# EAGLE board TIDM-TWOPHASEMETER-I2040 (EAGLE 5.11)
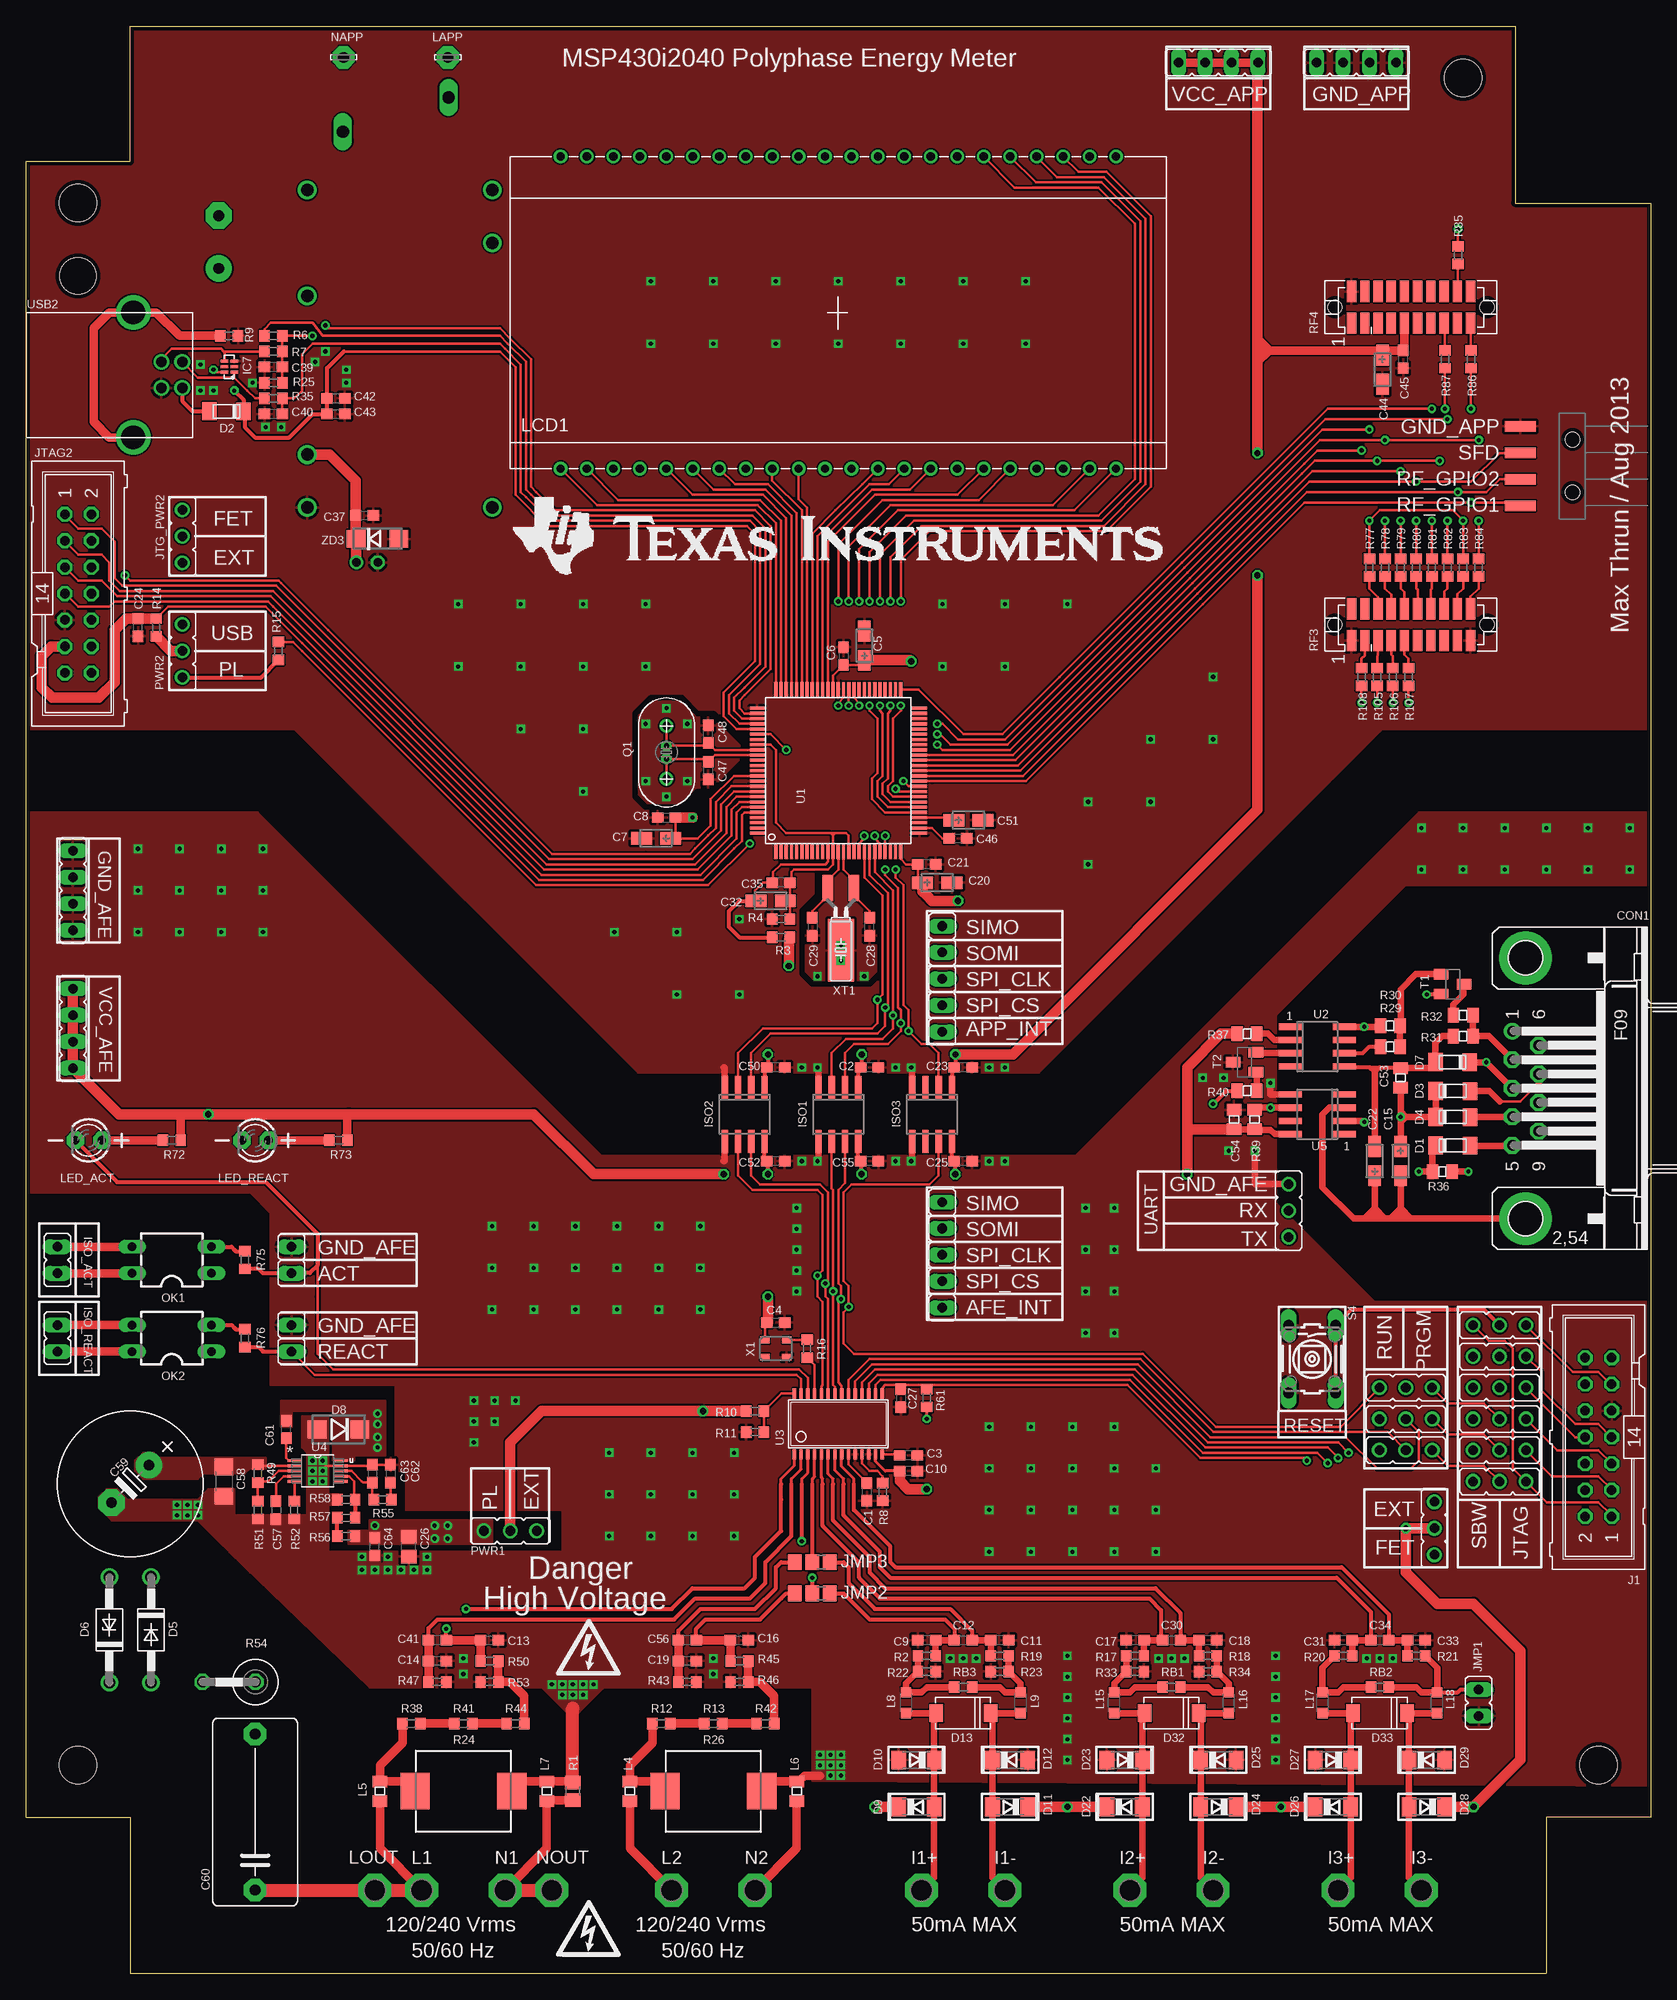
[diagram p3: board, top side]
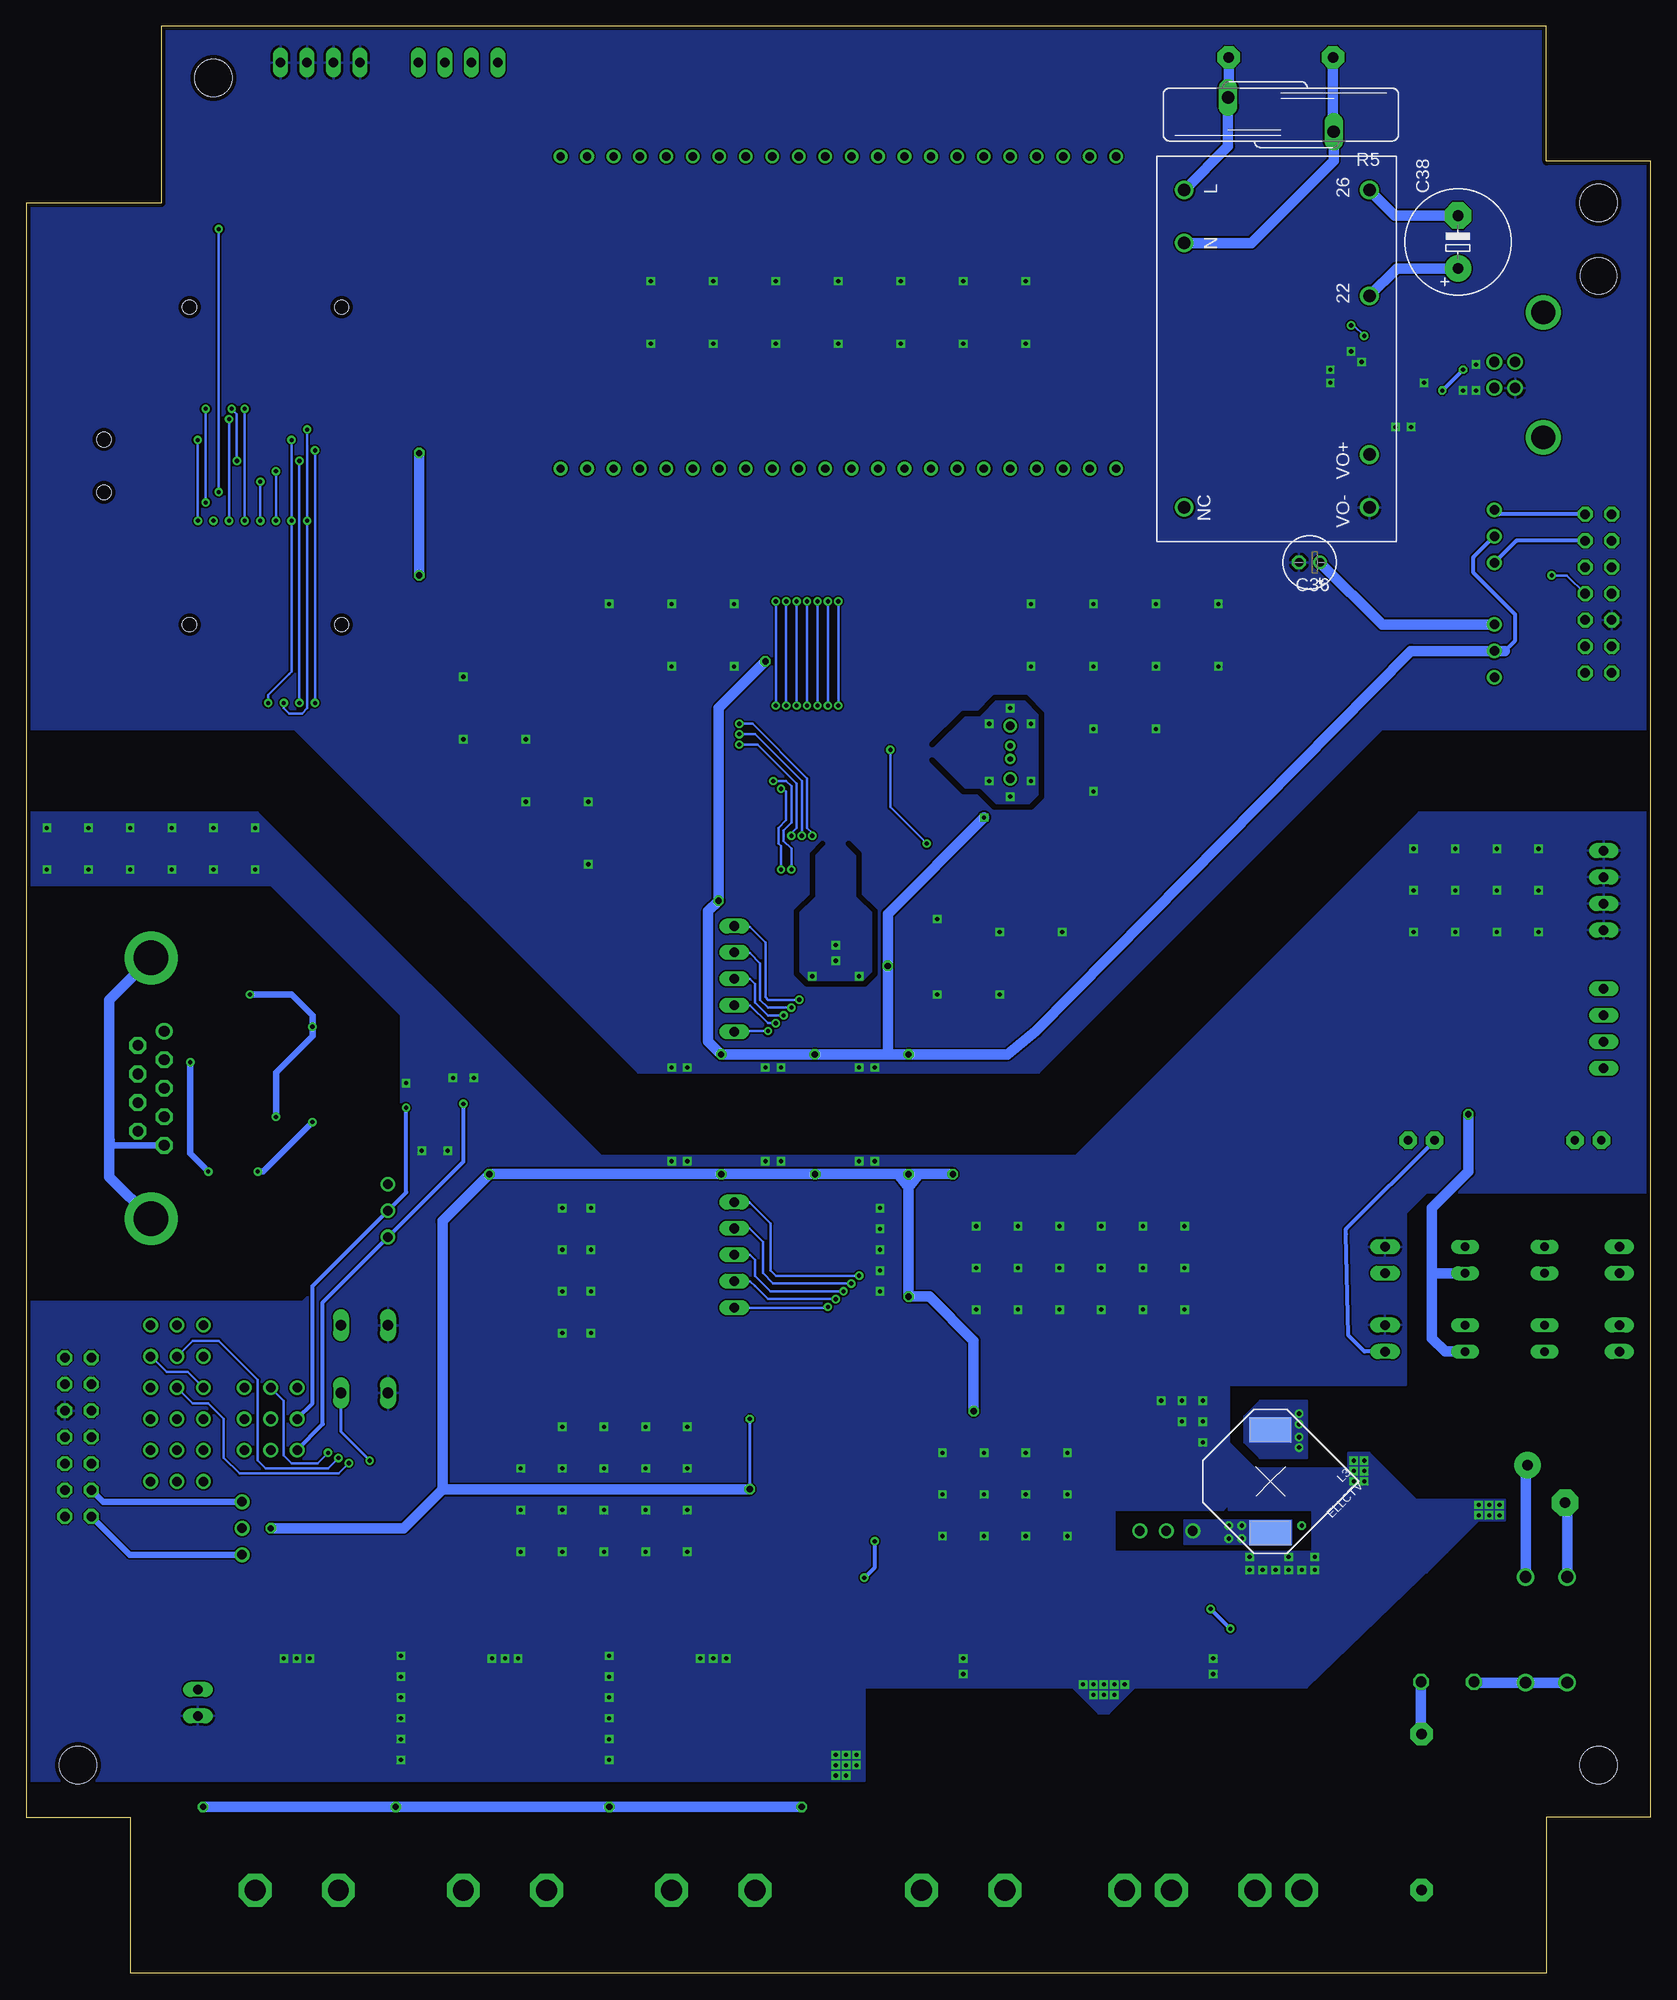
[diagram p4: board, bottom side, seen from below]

Size 156 x 187 mm. Coordinates in mm from the lower left corner, seen from the top.
Copper layers (1*16): Top 0.0356mm / dielectric 1.5011mm / Bottom 0.0356mm
Design rules "typical_4pcb": minimum track width 10mil, minimum drill 15mil, track to track 6mil, track to pad 6mil, pad to pad 6mil, via to via 6mil, smd to smd 6mil, copper to edge 15mil, drill to drill 8mil, minimum pad ring 10mil, minimum via ring 8mil, stop-mask expansion 4mil, vias tented up to drill 25mil, thermal gap 10mil
tRestrict: 20 lines
bRestrict: area 63.2,22.1 to 64.8,23.6; 22 lines

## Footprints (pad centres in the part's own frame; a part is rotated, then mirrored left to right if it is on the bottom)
JP1 = drill 0.914 long: 1 0,-1.27; 2 0,1.27
C0603 = smd 1.1 x 1: 1 -0.85,0; 2 0.85,0
CT3216 = smd 2 x 1.2: + -1.4,0; - 1.4,0
C0805 = smd 1.3 x 1.5: 1 -0.95,0; 2 0.95,0
E2-5 = drill 0.813 pad 1.27 round: + -1.016,0 | drill 0.813 pad 1.27 octagon: - 1.016,0
E5-10,5 = drill 1.016 pad 2.54 round: + -2.54,0 | drill 1.016 pad 2.54 octagon: - 2.54,0
CSMD0805 = smd 1.092 x 1.397: 1 -0.94,0; 2 0.94,0
C1206 = smd 1.6 x 1.8: 1 -1.4,0; 2 1.4,0
E5-13 = drill 1.016 pad 2.54 round: + -2.54,0 | drill 1.016 pad 2.54 octagon: - 2.54,0
C15B8 = drill 1.016 pad 2.159 octagon: 1 -7.493,0; 2 7.493,0
3_PHASE_CASE = hole 3.6: 0,0; 146,0; 0,150; 133,162 | hole 3.5: 0,143
JP5 = drill 0.914 long: 1 -5.08,0; 2 -2.54,0; 3 0,0; 4 2.54,0; 5 5.08,0
F09HP = drill 1.016 pad 1.6 round: 1 -5.486,-1.27 | drill 1.016 pad 1.6 octagon: 2 -2.743,-1.27; 3 0,-1.27; 4 2.743,-1.27; 5 5.486,-1.27; 6 -4.115,1.27; 7 -1.372,1.27; 8 1.372,1.27; 9 4.115,1.27 | drill 3.302 pad 5.08 round: G1 -12.522,0; G2 12.522,0
SOD-80 = smd 1.397 x 1.702: 1 1.397,-0.025; 2 -1.88,0
DO41-10 = drill 1.118 round: A 5.08,0; C -5.08,0
DO41Z10 = drill 1.118 round: A 5.08,0; C -5.08,0
DO214BA = smd 1.8 x 1.7: A 2.05,0; C -2.05,0
SOD80C = smd 1.4 x 1.8: A -1.7,0; C 1.7,0
DO-214 = smd 1.3 x 1.7: 1 0,0; 2 5.2,0
JP4 = drill 0.914 long: 1 -3.81,0; 2 -1.27,0; 3 1.27,0; 4 3.81,0
JP2 = drill 0.914 round: 1 -2.54,0; 2 0,0; 3 2.54,0
P1-20 = drill 2.007 pad 3.15 octagon: TP 0,0
DRY6 = smd 0.3 x 0.7: 1 -0.98,-2.254; 2 -0.457,-2.254; 3 0.066,-2.254; 4 0.066,-1.306; 5 -0.459,-1.306; 6 -0.98,-1.306
SO-08 = smd 0.6 x 2.2: 1 -1.905,-2.6; 2 -0.635,-2.6; 3 0.635,-2.6; 4 1.905,-2.6; 5 1.905,2.6; 6 0.635,2.6; 7 -0.635,2.6; 8 -1.905,2.6
ML14 = drill 0.914 octagon: 1 -7.62,-1.27; 2 -7.62,1.27; 3 -5.08,-1.27; 4 -5.08,1.27; 5 -2.54,-1.27; 6 -2.54,1.27; 7 0,-1.27; 8 0,1.27; 9 2.54,-1.27; 10 2.54,1.27; 11 5.08,-1.27; 12 5.08,1.27; 13 7.62,-1.27; 14 7.62,1.27
A0R-JMP = smd 1.5 x 1.3: 1 0,1.7; 2 0,0; 3 0,-1.7
1X04-SMD = smd 1 x 3: 1 -3.81,5; 2 -1.27,5; 3 1.27,5; 4 3.81,5 | hole 1.4: -2.54,0; 2.54,0
ELLCTV = smd 2.4 x 4 rotated 45: 1 -3.5,-3.5; 2 3.5,3.5
0805@1 = smd 1.092 x 1.397: 1 -0.94,0; 2 0.94,0
L2012C = smd 1 x 1: 1 -1,0; 2 1,0
LSP10 = drill 1.016 pad 2.159 octagon: MP 0,0
TI_160SEG_LCD = drill 0.8 round: 1 4.826,0; 2 7.366,0; 3 9.906,0; 4 12.446,0; 5 14.986,0; 6 17.526,0; 7 20.066,0; 8 22.606,0; 9 25.146,0; 10 27.686,0; 11 30.226,0; 12 32.766,0; 13 35.306,0; 14 37.846,0; 15 40.386,0; 16 42.926,0; 17 45.466,0; 18 48.006,0; 19 50.546,0; 20 53.086,0; 21 55.626,0; 22 58.166,0; 23 58.166,29.972; 24 55.626,29.972; 29 42.926,29.972; 30 40.386,29.972; 31 37.846,29.972; 32 35.306,29.972; 33 32.766,29.972; 34 30.226,29.972; 35 27.686,29.972; 36 25.146,29.972; 37 22.606,29.972; 38 20.066,29.972; 39 17.526,29.972; 40 14.986,29.972; 41 12.446,29.972; 42 9.906,29.972; 43 7.366,29.972; 44 4.826,29.972; COM0 45.466,29.972; COM1 48.006,29.972; COM2 50.546,29.972; COM3 53.086,29.972
LED3MM = drill 0.8 pad 1.676 octagon: A -1.27,0; K 1.27,0
DIL04 = drill 0.813 long: 1 -3.81,1.27; 2 -3.81,-1.27; 3 3.81,-1.27; 4 3.81,1.27
HCTC = drill 0.5 round: 1 -0.635,0; 2 0.635,0 | drill 0.8 round: 3 -2.54,0; 4 2.54,0
R0805 = smd 1.3 x 1.5: 1 -0.85,0; 2 0.85,0
R0603 = smd 1 x 1.1: 1 -0.85,0; 2 0.85,0
S20K275 = drill 1.194 long: 1 -1.651,-5.08; 2 1.651,5.08
CU4032K = smd 2.8 x 3.5: 1 -4.65,0; 2 4.65,0
0805 = smd 1.092 x 1.397: 1 -0.94,0; 2 0.94,0
0414V = drill 1.016 octagon: 1 -2.54,0; 2 2.54,0
TFM-110-02-SM-D-A-K = smd 2.032 x 0.889: 1 -1.524,5.715; 2 1.524,5.715; 3 -1.524,4.445; 4 1.524,4.445; 5 -1.524,3.175; 6 1.524,3.175; 7 -1.524,1.905; 8 1.524,1.905; 9 -1.524,0.635; 10 1.524,0.635; 11 -1.524,-0.635; 12 1.524,-0.635; 13 -1.524,-1.905; 14 1.524,-1.905; 15 -1.524,-3.175; 16 1.524,-3.175; 17 -1.524,-4.445; 18 1.524,-4.445; 19 -1.524,-5.715; 20 1.524,-5.715 | hole 1.359: 0,7.303; 0,-7.303
B3F-10XX = drill 1.016 long: 1 -3.251,2.261; 2 3.251,2.261; 3 -3.251,-2.261; 4 3.251,-2.261
SOT23-BEC = smd 1 x 1.4: B -0.95,-1.1; C 0,1.1; E 0.95,-1.1
PZ100 = smd 1.4 x 0.3: 1 -7.8,6; 2 -7.8,5.5; 3 -7.8,5; 4 -7.8,4.5; 5 -7.8,4; 6 -7.8,3.5; 7 -7.8,3; 8 -7.8,2.5; 9 -7.8,2; 10 -7.8,1.5; 11 -7.8,1; 12 -7.8,0.5; 13 -7.8,0; 14 -7.8,-0.5; 15 -7.8,-1; 16 -7.8,-1.5; 17 -7.8,-2; 18 -7.8,-2.5; 19 -7.8,-3; 20 -7.8,-3.5; 21 -7.8,-4; 22 -7.8,-4.5; 23 -7.8,-5; 24 -7.8,-5.5; 25 -7.8,-6; 51 7.8,-6; 52 7.8,-5.5; 53 7.8,-5; 54 7.8,-4.5; 55 7.8,-4; 56 7.8,-3.5; 57 7.8,-3; 58 7.8,-2.5; 59 7.8,-2; 60 7.8,-1.5; 61 7.8,-1; 62 7.8,-0.5; 63 7.8,0; 64 7.8,0.5; 65 7.8,1; 66 7.8,1.5; 67 7.8,2; 68 7.8,2.5; 69 7.8,3; 70 7.8,3.5; 71 7.8,4; 72 7.8,4.5; 73 7.8,5; 74 7.8,5.5; 75 7.8,6 | smd 0.3 x 1.4: 26 -6,-7.8; 27 -5.5,-7.8; 28 -5,-7.8; 29 -4.5,-7.8; 30 -4,-7.8; 31 -3.5,-7.8; 32 -3,-7.8; 33 -2.5,-7.8; 34 -2,-7.8; 35 -1.5,-7.8; 36 -1,-7.8; 37 -0.5,-7.8; 38 0,-7.8; 39 0.5,-7.8; 40 1,-7.8; 41 1.5,-7.8; 42 2,-7.8; 43 2.5,-7.8; 44 3,-7.8; 45 3.5,-7.8; 46 4,-7.8; 47 4.5,-7.8; 48 5,-7.8; 49 5.5,-7.8; 50 6,-7.8; 76 6,7.8; 77 5.5,7.8; 78 5,7.8; 79 4.5,7.8; 80 4,7.8; 81 3.5,7.8; 82 3,7.8; 83 2.5,7.8; 84 2,7.8; 85 1.5,7.8; 86 1,7.8; 87 0.5,7.8; 88 0,7.8; 89 -0.5,7.8; 90 -1,7.8; 91 -1.5,7.8; 92 -2,7.8; 93 -2.5,7.8; 94 -3,7.8; 95 -3.5,7.8; 96 -4,7.8; 97 -4.5,7.8; 98 -5,7.8; 99 -5.5,7.8; 100 -6,7.8
SO08 = smd 0.6 x 2.2: 1 -1.905,-2.6; 2 -0.635,-2.6; 3 0.635,-2.6; 4 1.905,-2.6; 5 1.905,2.6; 6 0.635,2.6; 7 -0.635,2.6; 8 -1.905,2.6
TSSOP28 = smd 0.305 x 0.991: 1 -0.415,-1.648; 2 0.235,-1.648; 3 0.885,-1.648; 4 1.535,-1.648; 5 2.185,-1.648; 6 2.835,-1.648; 7 3.485,-1.648; 8 4.135,-1.648; 9 4.785,-1.648; 10 5.435,-1.648; 11 6.085,-1.648; 12 6.735,-1.648; 13 7.385,-1.648; 14 8.035,-1.648; 15 8.035,4.188; 16 7.385,4.188; 17 6.735,4.188; 18 6.085,4.188; 19 5.435,4.188; 20 4.785,4.188; 21 4.135,4.188; 22 3.485,4.188; 23 2.835,4.188; 24 2.185,4.188; 25 1.535,4.188; 26 0.885,4.188; 27 0.235,4.188; 28 -0.415,4.188
DGQ10_1P88X1P57 = smd 1.422 x 0.279: 1 -2.184,0.991; 2 -2.184,0.508; 3 -2.184,0; 4 -2.184,-0.508; 5 -2.184,-0.991; 6 2.184,-0.991; 7 2.184,-0.508; 8 2.184,0; 9 2.184,0.508; 10 2.184,0.991
CUI_XR = drill 1.2 round: 22 10.16,0; 26 0,0; L 0,-17.78; N 5.08,-17.78; NC 30.48,-17.78; VO+ 25.4,0; VO- 30.48,0
USB_BUCHSE = drill 1 round: 1 1.25,7; 2 -1.25,7; 3 -1.25,5; 4 1.25,5 | drill 2.3 round: 5 -6,2.3; 6 6,2.3
ASE = smd 0.9 x 0.65: 1 -1.05,-0.825; 2 1.05,-0.825; 3 1.05,0.825; 4 -1.05,0.825
CM200T = smd 1 x 2.5: P1 -1.25,-5; P2 1.25,-5 | smd 2.5 x 6: P3 0,1
DO214AC = smd 1.8 x 1.7: A 2.05,0; C -2.05,0

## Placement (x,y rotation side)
ACT  [JP1]  25.5,68.5 0 top
C1  100nF  [C0603]  80.75,46.25 90 top
C2  0.1u  [C0603]  81,87 180 top
C3  470n  [C0603]  84.75,49.75 180 top
C4  0.01uF  [C0603]  72,62.5 0 top
C5  10u  [CT3216]  80.5,127.5 90 top
C6  0.1u  [C0603]  78.5,126.5 270 top
C7  10u  [CT3216]  60.5,109 180 top
C8  0.1u  [C0603]  61.5,111 0 top
C9  47pF  [C0603]  86.5,32 180 top
C10  4.7u  [C0603]  84.75,48.25 180 top
C11  47pF  [C0603]  93.5,32 180 top
C12  15nF  [C0603]  90,32 0 top
C13  47pF  [C0603]  44.5,32 0 top
C14  47pF  [C0603]  39.5,30 180 top
C15  10u  [CT3216]  132,78 270 top
C16  47pF  [C0603]  68.5,32 0 top
C17  47pF  [C0603]  106.5,32 180 top
C18  47pF  [C0603]  113.5,32 180 top
C19  47pF  [C0603]  63.5,30 180 top
C20  10u  [CT3216]  87.5,104.75 0 top
C21  0.1u  [C0603]  86.5,106.5 180 top
C22  10u  [CT3216]  129.5,78 90 top
C23  0.1u  [C0603]  90,87 180 top
C24  2.2n  [C0603]  10.75,129.25 90 top
C25  0.1u  [C0603]  90,78 180 top
C26  DNP  [C0805]  36.75,41 90 top
C27  2.2nF DNP  [C0603]  84,55.25 270 top
C28  12pF  [C0603]  81,100.5 90 top
C29  12pF  [C0603]  75.5,100.5 270 top
C30  15nF  [C0603]  110,32 0 top
C31  47pF  [C0603]  126.5,32 180 top
C32  10u  [CT3216]  71.5,103 0 top
C33  47pF  [C0603]  133.5,32 180 top
C34  15nF  [C0603]  130,32 0 top
C35  0.1u  [C0603]  72.5,104.75 180 top
C36  150uF  [E2-5]  32.75,135.5 180 bottom
C37  0.1u  [C0603]  32.5,140 0 top
C38  4.7u/400V  [E5-10,5]  18.5,166.25 90 bottom
C39  10p  [C0603]  23.75,154.25 180 top
C40  10p  [C0603]  23.75,149.75 180 top
C41  15nF  [C0603]  39.5,32 180 top
C42  4.7u  [C0603]  29.75,151.25 0 top
C43  0.1u  [C0603]  29.75,149.75 0 top
C44  10u  [CT3216]  130.25,154 270 top
C45  0.1u  [C0603]  132.25,155 90 top
C46  470n  [C0603]  89.5,109 0 top
C47  47pF  [C0603]  65.5,115.5 270 top
C48  47pF  [C0603]  65.5,119 90 top
C50  0.1u  [C0603]  72,87 180 top
C51  10u  [CT3216]  90.5,110.75 0 top
C52  0.1u  [C0603]  72,78 180 top
C53  0.1u  [CSMD0805]  132,86 90 top
C54  0.1u  [CSMD0805]  116,82 270 top
C55  0.1u  [C0603]  81,78 180 top
C56  15nF  [C0603]  63.5,32 180 top
C57  0.047uF  [C0603]  24,44.5 270 top
C58  2.2uF  [C1206]  19,47.25 270 top
C59  220uF/100V  [E5-13]  10,47 225 top
C60  0.22uF/305VAC  [C15B8]  22,15.5 90 top
C61  0.047uF  [C0603]  25,52.25 90 top
C62  0.047uF  [C0603]  35,48 270 top
C63  0.047uF  [C0603]  33.25,48 270 top
C64  2.2uF  [C0603]  33.5,41 90 top
CASE1  3_PHASE_CASE  [3_PHASE_CASE]  5,20 0 top
COMMS_AFE  [JP5]  88,69 270 top
COMMS_APP  JP5E  [JP5]  88,95.5 270 top
CON1  F09HP  [F09HP]  144,85 270 top
D1  LL103A  [SOD-80]  137.25,79.5 0 top
D2  LL103A  [SOD-80]  19,150 180 top
D3  LL103A  [SOD-80]  137.25,84.75 0 top
D4  LL103A  [SOD-80]  137.25,82.25 0 top
D5  1N4004  [DO41-10]  12,33 270 top
D6  1N4728  [DO41Z10]  8,33 90 top
D7  LL103A  [SOD-80]  136.75,87.5 180 top
D8  B150  [DO214BA]  30,52.25 180 top
D9  1N4148  [SOD80C]  85.5,16 180 top
D10  1N4148  [SOD80C]  85.5,20.5 0 top
D11  1N4148  [SOD80C]  94.5,16 0 top
D12  1N4148  [SOD80C]  94.5,20.5 180 top
D13  SMAJ5.0CA  [DO-214]  92.62,25 180 top
D22  1N4148  [SOD80C]  105.5,16 180 top
D23  1N4148  [SOD80C]  105.5,20.5 0 top
D24  1N4148  [SOD80C]  114.5,16 0 top
D25  1N4148  [SOD80C]  114.5,20.5 180 top
D26  1N4148  [SOD80C]  125.5,16 180 top
D27  1N4148  [SOD80C]  125.5,20.5 0 top
D28  1N4148  [SOD80C]  134.5,16 0 top
D29  1N4148  [SOD80C]  134.5,20.5 180 top
D32  SMAJ5.0CA  [DO-214]  112.62,25 180 top
D33  SMAJ5.0CA  [DO-214]  132.62,25 180 top
DGND2  [JP4]  127.75,183.5 0 top
DVCC2  [JP4]  114.5,183.5 0 top
FSEL1  HEADER0.05  [JP2]  132.5,50.25 180 top
FSEL2  HEADER0.05  [JP2]  132.5,53.25 180 top
FSEL3  HEADER0.05  [JP2]  132.5,56.25 180 top
GND_AFE  [JP4]  4.5,104 270 top
I1+  TPSQPAD1-20  [P1-20]  86,8 0 top
I1-  TPSQPAD1-20  [P1-20]  94,8 0 top
I2+  TPSQPAD1-20  [P1-20]  106,8 0 top
I2-  TPSQPAD1-20  [P1-20]  114,8 0 top
I3+  TPSQPAD1-20  [P1-20]  126,8 0 top
I3-  TPSQPAD1-20  [P1-20]  134,8 0 top
IC7  TPD4E004  [DRY6]  17.75,154.75 90 top
ISO1  ISO7420FE  [SO-08]  78,82.5 180 top
ISO2  ISO7421FE  [SO-08]  69,82.5 180 top
ISO3  ISO7421FE  [SO-08]  87,82.5 180 top
ISO_ACT  [JP1]  3,68.5 0 top
ISO_REACT  [JP1]  3,61 0 top
J1  [ML14]  151,51.5 90 top
JMP1  [JP1]  139.5,26 0 top
JMP2  0R-JUMPA  [A0R-JMP]  75.5,36.5 270 top
JMP3  0R-JUMPA  [A0R-JMP]  75.5,39.5 270 top
JP2  [1X04-SMD]  148.5,144.75 90 top
JTAG2  ML14  [ML14]  5,132.5 270 top
JTAG_SEL1  HEADER0.05  [JP2]  141.5,56.25 180 top
JTAG_SEL2  HEADER0.05  [JP2]  141.5,62.25 180 top
JTAG_SEL3  HEADER0.05  [JP2]  141.5,59.25 180 top
JTAG_SEL4  HEADER0.05  [JP2]  141.5,53.25 180 top
JTAG_SEL5  HEADER0.05  [JP2]  141.5,50.25 180 top
JTAG_SEL6  HEADER0.05  [JP2]  141.5,47.25 180 top
JTG_PWR1  [JP2]  135.25,42.75 90 top
JTG_PWR2  [JP2]  15,138 270 top
L1  TPSQPAD1-20  [P1-20]  38,8 0 top
L2  TPSQPAD1-20  [P1-20]  62,8 0 top
L3  ELLCTV  [ELLCTV]  36.5,47.25 225 bottom
L4  0  [0805@1]  58,17.5 90 top
L5  0  [0805@1]  34,17.5 90 top
L6  0  [0805@1]  74,17.5 90 top
L7  0  [0805@1]  50,17.5 90 top
L8  0  [L2012C]  84.5,26 90 top
L9  0  [L2012C]  95.5,26 90 top
L15  0  [L2012C]  104.5,26 90 top
L16  0  [L2012C]  115.5,26 90 top
L17  0  [L2012C]  124.5,26 90 top
L18  0  [L2012C]  135.5,26 90 top
LAPP  LSP10  [LSP10]  40.5,184 0 top
LCD1  TI_160SEG_LCD  [TI_160SEG_LCD]  46.5,144.5 0 top
LED_ACT  [LED3MM]  6,80 180 top
LED_REACT  [LED3MM]  22,80 180 top
LOUT  TPSQPAD1-20  [P1-20]  33.5,8 0 top
N1  TPSQPAD1-20  [P1-20]  46,8 0 top
N2  TPSQPAD1-20  [P1-20]  70,8 0 top
NAPP  LSP10  [LSP10]  30.5,184 0 top
NOUT  TPSQPAD1-20  [P1-20]  50.5,8 0 top
OK1  TIL191  [DIL04]  14,68.5 180 top
OK2  TIL191  [DIL04]  14,61 180 top
PWR1  [JP2]  46.5,42.5 0 top
PWR2  [JP2]  15,127 270 top
Q1  HCTC_XTL_4  [HCTC]  61.5,117.25 90 top
R1  0  [R0805]  52.5,17.5 270 top
R2  1K  [R0603]  86.5,30.5 180 top
R3  10  [R0603]  72.5,99.5 180 top
R4  0  [R0603]  72.5,101.25 0 top
R5  S20K275  [S20K275]  35.5,178.5 90 bottom
R6  1.4k  [R0603]  23.75,157.25 0 top
R7  27  [R0603]  23.75,155.75 180 top
R8  20k  [R0603]  82.25,46.25 270 top
R9  33k  [R0603]  19.5,157.25 180 top
R10  DNP  [R0603]  70,54 180 top
R11  DNP  [R0603]  70,52 180 top
R12  330k  [R0603]  61,24 0 top
R13  330k  [R0603]  66,24 0 top
R14  47k  [R0603]  12.5,129.25 90 top
R15  0  [R0603]  24.25,127 90 top
R16  0  [R0603]  75,60 270 top
R17  1K  [R0603]  106.5,30.5 180 top
R18  1K  [R0603]  113.5,30.5 0 top
R19  1K  [R0603]  93.5,30.5 0 top
R20  1K  [R0603]  126.5,30.5 0 top
R21  1K  [R0603]  133.5,30.5 180 top
R22  DNP  [R0603]  86.5,29 180 top
R23  0  [R0603]  93.5,29 180 top
R24  VARISTORCU4032K  [CU4032K]  42,17.5 0 top
R25  1M  [R0603]  23.75,152.75 0 top
R26  VARISTORCU4032K  [CU4032K]  66,17.5 0 top
R29  1k  [0805]  131,89 0 top
R30  10k  [0805]  131,91 180 top
R31  1.5k  [0805]  138,90 0 top
R32  220  [0805]  138,92 180 top
R33  DNP  [R0603]  106.5,29 180 top
R34  0  [R0603]  113.5,29 180 top
R35  27  [R0603]  23.75,151.25 180 top
R36  1k  [0805]  136,77 0 top
R37  68  [0805]  117.25,90.25 0 top
R38  330k  [R0603]  37,24 0 top
R39  2.2k  [0805]  118,82 90 top
R40  2.2k  [0805]  117.25,84.75 0 top
R41  330k  [R0603]  42,24 0 top
R42  330k  [R0603]  71,24 0 top
R43  1K  [R0603]  63.5,28 0 top
R44  330k  [R0603]  47,24 0 top
R45  100  [R0603]  68.5,30 180 top
R46  2.7k  [R0603]  68.5,28 0 top
R47  1K  [R0603]  39.5,28 0 top
R49  1.8M  [R0603]  22.25,48 270 top
R50  100  [R0603]  44.5,30 180 top
R51  59k  [R0603]  22.25,44.5 270 top
R52  332k  [R0603]  25.75,44.5 270 top
R53  2.7k  [R0603]  44.5,28 0 top
R54  560R/3W  [0414V]  19.5,28 180 top
R55  332k  [R0603]  34.25,45.5 0 top
R56  51  [R0603]  30.75,42 180 top
R57  316k  [R0603]  30.75,43.75 0 top
R58  100k  [R0603]  30.75,45.5 180 top
R61  47k  [R0603]  86.5,55.25 90 top
R72  1K  [R0603]  14,80 0 top
R73  1K  [R0603]  30,80 0 top
R75  1K  [R0603]  21,68.5 90 top
R76  1K  [R0603]  21,61 90 top
R77  0  [R0603]  129,135 90 top
R78  0  [R0603]  130.5,135 90 top
R79  0  [R0603]  132,135 90 top
R80  0  [R0603]  133.5,135 90 top
R81  0  [R0603]  135,135 90 top
R82  0  [R0603]  136.5,135 90 top
R83  0  [R0603]  138,135 90 top
R84  0  [R0603]  139.5,135 90 top
R85  0  [R0603]  137.5,165 270 top
R86  0  [R0603]  138.75,155 270 top
R87  0  [R0603]  136.25,155 270 top
R105  0  [R0603]  129.75,124.5 90 top
R106  0  [R0603]  131.25,124.5 90 top
R107  0  [R0603]  132.75,124.5 90 top
R108  0  [R0603]  128.25,124.5 90 top
RB1  13  [R0603]  110,27.5 180 top
RB2  13  [R0603]  130,27.5 0 top
RB3  13  [R0603]  90,27.5 180 top
REACT  [JP1]  25.5,61 0 top
RF3  [TFM-110-02-SM-D-A-K]  133,129.51 90 top
RF4  [TFM-110-02-SM-D-A-K]  133,159.99 90 top
S4  [B3F-10XX]  123.5,59 270 top
T1  BC860B/BC857B  [SOT23-BEC]  137,95 270 top
T2  BC860B/BC857B  [SOT23-BEC]  117,87.5 90 top
U1  F66XX---PZ100  [PZ100]  78,115.5 90 top
U2  PS8802  [SO08]  124,89 270 top
U3  MSP430I2040XPW  [TSSOP28]  74.19,51.5 0 top
U4  TPS5401_DGQ_10  [DGQ10_1P88X1P57]  28,48.25 0 top
U5  PS8802  [SO08]  124,82.5 90 top
U$2  CUI_XR  [CUI_XR]  27,171.25 270 bottom
UART  HEADER0.05  [JP2]  121.25,73.25 90 top
USB2  [USB_BUCHSE]  8,153.5 270 top
VCC_AFE  [JP4]  4.5,90.75 90 top
X1  ASE  [ASE]  72,60 0 top
XT1  XT1  [CM200T]  78.25,99.25 180 top
ZD3  SMAJ5.0ABCT  [DO214AC]  33.75,137.75 0 top

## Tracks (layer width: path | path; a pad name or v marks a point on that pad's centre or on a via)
+12V  (via drill 0.4)
  Top 0.406: v128.5,90.91 129.5,90.91 129.97,90.91 R30.2 | T1.E 134.55,94.05 v134.5,94
  Top 0.61: D3.2 D4.2 132.5,82.25 | C15.+ 132,81.5 132,81.75 | U2.8 v128.5,90.91 129.5,90.91 | v132,82.25 132,82.75 | 132,82.75 C53.1 | 132,81.75 v132,82.25 | v132,82.25 132,82.75 | v132,82.25 132,82.75 | 132.5,82.25 132,82.75 | 132,81.75 132.5,82.25
  Bottom 0.61: v134.5,94 130.5,94 128.5,92 v128.5,90.91 128.5,90 132,86.5 v132,82.25
+12V1
  Top 0.254: 145.27,85.52 143.5,83.75 141.5,83.75
  Top 0.61: 145.27,85.52 CON1.7 | D3.1 140.53,84.72 141.5,83.75
+12V3
  Top 0.254: 142.7,82.22 CON1.4
  Top 0.61: D4.1 142.7,82.22
-12V
  Top 0.406: 129,87 129.5,86.5 130,87 | 129,87 126.69,87 U2.5 | 130,87 131.94,87 C53.2 | 129,87 130,87 | 134.77,86.94 D7.1
  Top 0.61: D7.1 135.35,89.35 136,90 R31.1 | C22.- 129.5,86.5 | C53.2 134.77,86.94
A0CLK  (via drill 0.4)
  Top 0.254: v87.5,120 88,120 89.5,118.5 94,118.5 111,135.5 124.75,149.25 v136.5,149.25 | U1.17 80,108.5 80.25,108.75 80.5,109 v80.5,109.25 | R82.2 v136.5,139.5
  Bottom 0.254: v80.5,109.25 80.5,109.5 81,110 81,114.75 86.25,120 v87.5,120 | v136.5,139.5 v136.5,149.25
A0CS  (via drill 0.4)
  Top 0.254: v135,150.25 125,150.25 99.25,124.5 93.75,119 90,119 85.7,123.3 U1.51 | R81.2 v135,139.5
  Bottom 0.254: v135,139.5 v135,150.25
A0SIMO  (via drill 0.4)
  Top 0.254: v87.5,119 87.75,119 88.75,118 94.25,118 111.25,135 124.5,148.25 v129,148.25 | U1.21 82,108.5 81.75,108.75 81.5,109 v81.5,109.25 | R77.2 v129,139.5 130,140.5 137,140.5 v138,139.5 R83.2 | v131.25,122 R106.1
  Bottom 0.254: v81.5,109.25 81.5,113.75 81.5,114.5 86,119 v87.5,119 | v129,148.25 129,146 v129,139.5 129,121.5 129.5,121 130,121 130.75,121 131.25,121.5 v131.25,122
A0SOMI  (via drill 0.4)
  Top 0.254: v82.5,109.25 U1.22 | v87.5,118 88,117.5 94.5,117.5 111.5,134.5 124.25,147.25 v130.5,147.25 v139.52,147.25 | v130.5,139.5 R78.2 | v139.5,139.5 R84.2 | R107.1 v132.75,122
  Bottom 0.254: v82.5,109.25 82.5,109.5 82,110 82,114.25 85.75,118 v87.5,118 | v139.52,147.25 139.52,139.52 v139.5,139.5 | v132.75,122 132.75,122.75 130.75,124.75 130.5,125 v130.5,139.5 v130.5,147.25
ACT_PUL
  Top 0.254: U3.26 75.08,57.17 74.25,58 29.5,58 28,59.5 28,64.98 28,68.25
  Top 0.406: R75.1 22.35,67.65 22.77,67.23 ACT.1 25.52,67.25 27.25,67.25 28,68 28,68.25 28,71 23,76 8.75,76 4.75,80 LED_ACT.K
AFE_INT  (via drill 0.4)
  Top 0.254: FSEL3.3 129.96,56.21 126.25,52.5 114.25,52.5 107.25,59.5 79.5,59.5 78.5,60.5 78.5,63.5 v79,64 79,66 78.5,66.5 78.5,75 79.25,75.75 86.75,75.75 87.64,76.64 ISO3.7
  Bottom 0.254: COMMS_AFE.5 79.08,63.92 v79,64
AGND_APP
  Top 0.254: U1.15 79,109.25 78.75,109.5 77.75,109.5 | 77.5,109.25 U1.12 77.5,106.5 77,106 76,106 73.75,106 73.5,105.75 73.5,104.9 C35.1 73.35,103.45 C32.- 73.35,102.55 R4.2 | U1.83 71.5,118 72,117.5 72,110.5 73,109.5 77.25,109.5 | 77.5,109.25 77.25,109.5 | 77.5,109.25 77.75,109.5 | 77.25,109.5 77.75,109.5
APP_INT  (via drill 0.4)
  Top 0.254: U1.34 83.75,113.5 v83.5,113.75 | ISO3.2 87.64,88.36 86.75,89.25 86,89.25 v84.75,90.5 | v83.5,106 83.5,105.25 84.25,104.5 84.25,94 84.25,93 84.75,92.5 v84.75,90.5 | v84.75,90.5 84.75,91.5
  Bottom 0.254: v83.5,113.75 83.25,113.75 83,113.5 83,110.75 83.75,110 83.75,108.5 83.5,108.25 v83.5,106 | v84.75,90.5 87.92,90.5 arc-90 COMMS_APP.5
AVCC_APP
  Top 0.254: U1.11 77,106.75 76.75,106.5 74.5,106.5 72.5,106.5 71.75,105.75 71.75,104.85 C35.2 70.75,104.75 70,104 70,103.1 C32.+
  Top 0.406: R3.2 68.5,99.5 67.5,100.5 67.5,102 68.5,103 C32.+
C  (via drill 0.4)
  Top 0.254: v126,49.5 125,50.5 120.5,50.5 120.25,50.5 113.25,50.5 106.25,57.5 81.75,57.5 80.92,56.67 U3.17
  Bottom 0.254: JTAG_SEL3.2 140,60.75 137.5,60.75 133.75,57 133.75,49.25 133,48.5 127,48.5 v126,49.5
CCA  (via drill 0.4)
  Top 0.254: U1.39 95.25,116 112.25,133 123.5,144.25 v132,144.25 | R79.2 v132,139.5
  Bottom 0.254: v132,139.5 v132,144.25
CLKIN
  Top 0.254: U3.25 75.72,58.42 R16.2
COM0  (via drill 0.4)
  Top 0.254: U1.30 82.5,111.5 81.25,112.75 81.25,114.75 81.75,115.25 81.75,120.5 81,121.25 v81,121.75 | v81,131.75 81,136.5 84.5,140 103,140 106.5,143.5 106.5,164.5 106.5,168 103,171.5 94.94,171.5 LCD1.COM0
  Bottom 0.254: v81,131.75 v81,121.75
COM1  (via drill 0.4)
  Top 0.254: U1.31 82.75,112 81.75,113 81.75,114.5 82.25,115 82.25,121 82,121.25 v82,121.75 | v82,131.75 82,136.25 85.25,139.5 103.25,139.5 107,143.25 107,164.75 107,168.25 103.25,172 96.98,172 LCD1.COM1
  Bottom 0.254: v82,131.75 v82,121.75
COM2  (via drill 0.4)
  Top 0.254: U1.32 83,112.5 82.25,113.25 82.25,114.25 82.75,114.75 82.75,121 83,121.25 v83,121.75 | v83,131.75 83,136 86,139 103.5,139 107.5,143 107.5,165 107.5,168.5 103.5,172.5 99.02,172.5 LCD1.COM2
  Bottom 0.254: v83,131.75 v83,121.75
COM3  (via drill 0.4)
  Top 0.254: U1.33 83.25,113 82.75,113.5 82.75,114 83.25,114.5 83.25,120.5 84,121.25 v84,121.75 | v84,131.75 84,135.75 86.75,138.5 103.75,138.5 108,142.75 108,165.25 108,166.06 108,168.75 103.75,173 101.06,173 LCD1.COM3
  Bottom 0.254: v84,131.75 v84,121.75
D+
  Top 0.254: IC7.4 19.06,155.44 19.06,155.69 19,155.75 | 19,155.75 R7.2 | USB2.3 13,155 14,156 18.75,156 19,155.75
D-
  Top 0.254: 20,153.25 17.5,153.25 16.5,153.25 USB2.2 | 20,153.25 21.25,152 22,151.25 R35.2 | IC7.1 20,153.25
DGND_APP  (via drill 0.4)
  Top 0.61: ISO2.4 67.09,87 67,87 | ISO1.4 76.09,87 v76,87 | ISO3.4 85.09,87 v85,87
  other vias: 21.75,152.75 18,152 16.75,154.5 74.5,87 83.5,87 92.5,87 94,87 30.75,154 30.75,152.75 27.75,154.75 28.75,155.75 68.5,101.25 16.75,152 23,148.5 24.5,148.5 47.5,131.5 47.5,125.5 53.5,125.5 53.5,131.5 53.5,119.5 47.5,119.5 53.5,113.5 88,131.5 94,131.5 88,125.5 94,125.5 100,131.5 114,124.5 114,118.5 108,112.5 108,118.5 102,112.5 102,106.5 56.5,100 62.5,100 62.5,94 68.5,94 41.5,131.5 59.5,131.5 41.5,125.5 59.5,125.5 63.5,120 63.5,114.5 59.5,120 59.5,114.5 61.5,121.5 61.5,113 76,95.75 80.5,95.75 78.25,98.75 78.25,97.25 72,156.5 78,156.5 78,162.5 72,162.5 84,162.5 84,156.5 66,162.5 66,156.5 60,156.5 60,162.5 90,162.5 96,162.5 90,156.5 96,156.5
  pour Top (isolate 0.127): 25.75,119.5 -1,119.5 -1,175 9,175 9,188 144,188 144,171 157,171 157,119.5 130.25,119.5 97.25,86.5 58.75,86.5
  pour Bottom (isolate 0.127): -1,119.5 -1,175 9,175 9,188 144,188 144,171 157,171 157,119.5 130.25,119.5 97.25,86.5 58.75,86.5 25.75,119.5
DVCC_APP  (via drill 0.4, 0.6)
  Top 0.254: U1.89 68,115 65.75,112.75 65.75,110.25 64.5,109 C7.+ 62.35,109.45 C8.2 | U1.64 77.5,124.65 C6.2 80.05,125.65 C5.+ | C20.+ 85.65,105.2 C21.2 84.5,106.5 84,107 U1.25
  Top 0.406: 89,85 ISO3.1 88.91,87 C23.2 89.25,87.35 v89.25,88.25 | ISO2.1 70.91,86.75 C50.2 71.25,87.1 v71.25,88.25 | ISO1.1 79.91,86.75 C2.2 80.25,87.1 v80.25,88.25
  Top 0.813: RF4.9 132.37,155.97 C45.2 130.7,155.85 | 130.7,155.85 C44.+ | 119.4,155.85 130.7,155.85 | 118.25,157 119.4,155.85 | 119.4,155.85 119.25,155.75 118.25,154.75 | 119.4,155.85 119.15,155.85 119,156 | DVCC2.1 DVCC2.2 DVCC2.3 DVCC2.4 | R3.1 73.35,99.35 73.25,99.25
  Top 1.016: PWR2.2 13.9,127 R14.1 | C5.+ 84.9,126.1 v85,126 | v89.5,103 87,103 86.5,103.5 86.1,103.9 C20.+ | DVCC2.4 118.31,183.31 118.25,183.25 118.25,157 118.25,154.75 v118.25,146 | v118.25,134.25 118.25,111.75 95,88.5 94.75,88.25 v89.25,88.25 | v73.25,96.75 73.25,99.25 | v64,111 C8.2
  Bottom 0.406: JTG_PWR2.2 17,136 17,134.5 13,130.5 13,128 14,127
  Bottom 0.813: 73,88.25 73.25,88.5
  Bottom 1.016: 14,127 PWR2.2 23,127 59,90.5 61.75,88.25 v71.25,88.25 73,88.25 v80.25,88.25 v89.25,88.25 90.5,89.5 90.5,102 v89.5,103 89.5,121.5 v85,126 | v118.25,146 v118.25,134.25 | 73.25,88.5 v73.25,96.75 73.25,101.75 v64,111
DVCC_APP_EXT
  Top 0.406: PWR2.3 22.56,124.46 R15.1
DVCC_APP_PL
  Top 1.016: C36.+ 31.7,135.53 ZD3.C 31.65,137.8 C37.1 31.65,143.35 31.5,143.5 29.15,145.85 U$2.VO+
  Bottom 1.016: PWR2.1 25.77,129.54 C36.+
DVCC_FET1
  Bottom 0.61: JTG_PWR1.1 146.06,40.21 J1.2
DVCC_FET2
  Bottom 0.406: JTAG2.2 14.58,140.12 JTG_PWR2.1
DVCC_PL  (via drill 0.4)
  other vias: 33.5,43 39.25,43 39.25,41.75 40.5,41.75 40.5,43
  pour Top (no thermals): 44.75,43.5 33,43.5 33,42.5 31,42.5 31,41.25 44.75,41.25
  pour Bottom (no thermals): 34.5,43.5 44.75,43.5 44.75,41.25 34.5,41.25
GND1
  Top 0.254: CON1.5 142.69,79.47
  Top 0.61: 142.69,79.47 D1.1 | 129.5,73.5 C22.+ 129.5,73.5 | 132,73.5 132,73.48 131.98,73.48 131,72.5 | 132,73.5 C15.- | U5.3 125.14,83.14 124.5,82.5 124.5,75.5 127.5,72.5 128.5,72.5 | 128.5,72.5 129.5,72.5 | 130.5,72.5 129.5,72.5 | 130.5,72.5 131,72.5 | 131,72.5 132,72.5 | 132,72.5 133,72.5 | 133,72.5 143.98,72.5 CON1.G2 | 129.5,73.5 128.5,72.5 | 129.5,73.5 130.5,72.5 | 129.5,73.5 129.5,72.5 | 133,72.5 132,73.5 | 132,72.5 132,73.5
  Bottom 0.61: CON1.5 147.99,79.51 148,79.5
  Bottom 1.016: CON1.G1 144,97.5 148,93.5 148,80 | 148,80 148,76.48 CON1.G2 | 147.99,79.51 147.99,79.99 148,80
GND_AFE  (via drill 0.4)
  Top 0.254: C62.1 C63.1 33.16,48.76 U4.9 28.76,48.76 28.75,48.75
  Top 0.61: ISO2.5 67.09,78 67,78 | ISO1.5 76.09,78 v76,78 | ISO3.5 85.09,78 v85,78 | U5.5 119.5,84.41 119.5,85 | UART.3 118,75.79 v118,79
  Top 0.813: L6.2 71.59,18.44 R26.2 | R24.2 47.59,18.44 L7.2 52.41,18.44 R1.1 | 74,18.5 74.25,18.5 74.75,19 76.25,19
  Top 1.016: L6.2 74,18.5
  Top 1.27: R1.1 52.5,25.5
  Bottom 1.016: D6.A 8,45 C59.-
  other vias: 88.75,30.25 90,30.25 91.25,30.25 108.75,30.25 110,30.25 111.25,30.25 128.75,30.25 130,30.25 131.25,30.25 66,30.25 66,28.75 42,28.75 42,30.25 44.75,71.75 56,50 101.75,61.5 74.5,78 83.5,78 92.5,78 94,78 32.25,40 34.75,40 33.5,38.75 27.5,49.25 28.5,49.25 28.5,48.25 27.5,48.25 27.5,47.25 28.5,47.25 32.25,38.75 34.75,38.75 14.5,45 14.5,44 15.5,44 15.5,45 16.5,45 16.5,44 44.75,67.75 48.75,71.75 52.75,71.75 48.75,67.75 52.75,67.75 52.75,63.75 48.75,63.75 44.75,63.75 56.75,63.75 56.75,67.75 56.75,71.75 60.75,71.75 60.75,67.75 60.75,63.75 101.75,65.5 101.75,69.5 101.75,73.5 56,46 56,42 60,50 64,50 64,46 60,46 60,42 64,42 68,46 68,42 68,50 74,73.5 74,71.5 74,69.5 74,67.5 74,65.5 64.75,71.75 64.75,67.75 64.75,63.75 43,55 43,53 45,55 47,55 43,51 45,53 104.5,61.5 104.5,65.5 104.5,69.5 104.5,73.5 92.5,48.5 92.5,44.5 96.5,48.5 100.5,48.5 96.5,44.5 100.5,44.5 100.5,40.5 96.5,40.5 92.5,40.5 104.5,40.5 104.5,44.5 104.5,48.5 108.5,48.5 108.5,44.5 108.5,40.5 100,20.5 100,22.5 100,24.5 100,26.5 100,28.5 100,30.5 120,20.5 120,22.5 120,24.5 120,26.5 120,28.5 120,30.5 22.75,100 22.75,104 18.75,100 14.75,100 18.75,104 14.75,104 14.75,108 18.75,108 22.75,108 10.75,108 10.75,104 10.75,100 76.25,20 76.25,21 77.25,21 77.25,20 77.25,19 78.25,21 78.25,20 78.25,19 51.5,26.75 52.5,26.75 53.5,26.75 53.5,27.75 51.5,27.75 52.5,27.75 50.5,27.75 54.5,27.75 92.5,52.5 96.5,52.5 100.5,52.5 104.5,52.5 115,86 119.5,85.5 115.5,79 113,86 154,110 154,106 150,106 150,110 146,110 146,106 142,110 142,106 138,106 138,110 134,110 134,106 36,38.75 37.25,38.75 38.5,38.75 38.5,40
  pour Top (isolate 0.127): 157,111.5 157,104.5 132.5,104.5 120,92 120,74 129.5,64.5 157,64.5 157,18 75.5,18.5 75.5,27.5 55.5,27.5 53,25 52,25 49.5,27.5 33,27.5 19.5,40.5 51.5,40.5 51.5,44.5 36.5,44.5 36.5,48.25 35,48.25 35,49.5 35.5,49.5 35.5,56.5 23.5,56.5 23.5,73 21.5,75 -1,75 -1,111.5 22.25,111.5 55.25,78.5 100.75,78.5 133.75,111.5
  pour Bottom (isolate 0.127): -1,111.5 -1,75 21.5,75 23.5,73 23.5,56.5 40.5,56.5 40.5,45 41,44.5 51.5,44.5 51.5,40.5 19.5,40.5 33,27.5 49.5,27.5 52,25 53,25 55.5,27.5 75.5,27.5 75.5,18.5 157,18.5 157,64.5 129.5,64.5 120,74 120,92 132.5,104.5 157,104.5 157,111.5 133.75,111.5 100.75,78.5 55.25,78.5 22.25,111.5
  pour Top (no thermals): 7.75,46.5 8.75,46.5 9.75,45.5 16.5,45.5 17.5,46.5 20,46.5 20,44 27,44 27,50 26.5,50.5 26.5,53.5 29,53.5 29,46 30,46 30,45 29,45 29,40.5 34,40.5 34,38.5 21.5,38.5 16.5,43.5 8.25,43.5 7,44.75 7,45.75
  pour Bottom (no thermals): 14,45.5 22.5,45.5 27,50 29,50 29,48.5 38,48.5 40.5,51 40.5,44.5 32.5,44.5 32.5,40.5 34,40.5 34,38.5 21.5,38.5 16.5,43.5 14,43.5
HFIN
  Top 0.254: Q1.4 Q1.2 65.23,117.89 C48.1 66.15,117.5 U1.84
HFOUT
  Top 0.254: Q1.3 Q1.1 65.23,116.61 C47.1 66.15,117 U1.85
I
  Top 0.254: JTAG_SEL5.2 140,51.75 136.54,51.75 FSEL2.1
I1+
  Top 0.406: C12.1 89.15,33.1 88.25,34 83.75,34 81,34 78.5,36.5 JMP2.1
  Top 0.61: R2.1 C9.1 C12.1
I1+/V2+  (via drill 0.4)
  Top 0.305: U3.3 75.08,48.08 74.5,47.5 74.5,47
  Top 0.406: JMP2.2 v75.5,38 | v74.5,41.5 74.5,43.5 74.5,45.5 74.5,47
  Bottom 0.406: v75.5,38 74.5,39 v74.5,41.5
I1-
  Top 0.406: C12.2 90.85,32.9 88.75,35 81.5,35 79,37.5 79,39 78.5,39.5 JMP3.1
  Top 0.61: C12.2 C11.2 R19.1
I1-/V2-
  Top 0.305: U3.4 75.72,47.73 75.5,47.5 75.5,47
  Top 0.406: JMP3.2 75.5,45 75.5,45.5 75.5,47
I2+
  Top 0.305: U3.5 76.38,47.62 76.5,47.5 76.5,47
  Top 0.406: 109,32 109,34.88 107.88,36 82,36 80,38 80,39.5 76.5,43 76.5,47
  Top 0.61: R17.1 C17.1 109,32 C30.1
I2-
  Top 0.305: U3.6 77.03,47.98 77.5,47.5 77.5,47
  Top 0.406: C30.2 110.85,34.62 108.47,37 82.5,37 81,38.5 81,40 77.5,43.5 77.5,47
  Top 0.61: C30.2 C18.2 R18.1
I3+
  Top 0.305: U3.7 77.67,48.33 78.5,47.5 78.5,47
  Top 0.406: C34.1 129.15,34.7 125.85,38 83,38 82,39 82,40.5 78.5,44 78.5,47
  Top 0.61: R20.2 C31.1 C34.1
I3-
  Top 0.305: U3.8 78.33,48.67 79.5,47.5 79.5,47
  Top 0.406: C34.2 130.85,34.5 126.35,39 83.5,39 83,39.5 83,41 79.5,44.5 79.5,47
  Top 0.61: C34.2 C33.2 R21.2
L_APP
  Bottom 1.016: LAPP.MP 40.5,180.23 R5.2 40.58,175.45 U$2.L
LCDCAP
  Top 0.254: U1.29 88.85,111 C51.+
LINE
  Top 0.813: L5.1 34,12 L1.TP
  Top 1.27: L1.TP LOUT.TP C60.1
LINE_1
  Top 0.813: R38.1 36.15,22.15 36,22 34,20 L5.2 36.41,18.44 R24.1
LINE_2
  Top 0.813: R26.1 60.41,18.44 L4.2 58,20 60.15,22.15 R12.1
M
  Top 0.254: JTAG_SEL4.2 140,54.75 136.54,54.75 FSEL3.1
M_SIMO  (via drill 0.4)
  Top 0.254: U1.18 80.5,105.25 82.25,103.5 82.25,94 v81.75,93.5 81.75,91.25 81.25,90.75 70.75,90.75 68.36,88.36 ISO2.3
  Bottom 0.254: v81.75,93.5 84.75,93.5 85,93.75 85,99 86.5,100.5 87.92,100.5 COMMS_APP.1
M_SOMI  (via drill 0.4)
  Top 0.254: U1.19 81,105.5 82.75,103.75 82.75,93 v82.5,92.75 82.5,91.75 82.5,91 81.75,90.25 71.5,90.25 69.64,88.39 ISO2.2
  Bottom 0.254: v82.5,92.75 84.75,92.75 85.5,93.5 85.5,97 86.5,98 87.96,98 COMMS_APP.2
MSPI_CLK  (via drill 0.4)
  Top 0.254: ISO1.3 77.36,88.36 78.75,89.75 82.25,89.75 83.25,90.75 v83.25,92 83.25,104 81.5,105.75 U1.20
  Bottom 0.254: v83.25,92 84.75,92 86,93.25 86,95 86.5,95.5 COMMS_APP.3
MSPI_CS  (via drill 0.4)
  Top 0.254: U1.35 84.75,114 v84.25,114.5 | ISO1.2 78.64,88.39 79.5,89.25 82.75,89.25 84,90.5 v84,91.25 84,92.5 83.75,92.75 83.75,104.25 82.5,105.5 v82.5,106
  Bottom 0.254: v84.25,114.5 83,114.5 82.5,114 82.5,110.5 83.25,109.75 83.25,108.75 82.5,108 v82.5,106 | COMMS_APP.4 86.46,92.96 84.75,91.25 v84,91.25
N1
  Top 0.813: N1.TP 50,12 L7.1 50.09,16.65 R1.2
  Top 1.27: N1.TP NOUT.TP
N$1
  Top 0.813: L4.1 58,12 L2.TP
N$2  (via drill 0.4)
  Top 0.406: 135.06,79.19 D1.2
  Top 0.61: 135.06,79.19 R36.1 v133.75,77 | U5.2 128.38,81.86 v128.5,81.75
  Bottom 0.61: v128.5,81.75 130.75,79.5 133.25,77 v133.75,77
N$3
  Top 0.61: L8.1 D13.2 87.2,24.77 D10.C D9.A 87.2,9.2 I1+.TP
N$4
  Top 0.406: U2.6 128.37,88.36 129,89 R29.1
N$5
  Top 0.406: 138,94.9 T1.C
  Top 0.61: R32.2 137.06,93.06 138,94 138,94.9
N$6
  Top 0.254: RF3.9 132.37,126.64 132.75,126.25 R107.2
N$7
  Top 0.254: R87.1 136.25,158.39 RF4.15
N$8
  Top 0.61: R40.2 118.19,86.46 T2.B
N$9
  Bottom 0.406: JTAG2.4 12.88,137.58 JTG_PWR2.3
N$10
  Top 0.813: R9.2 15.25,157.25 14.75,157.25 12.5,159.5 USB2.5 8,159.5 6.5,158 6.5,149 8,147.5 USB2.6
N$11
  Top 0.254: U1.27 87,110 88,109 C46.1
N$12
  Bottom 1.016: C38.- 24.54,168.79 U$2.26
N$13
  Bottom 1.016: C38.+ 24.38,163.71 U$2.22
N$14
  Top 0.254: U4.5 25.82,45.42 R52.1
N$15
  Top 0.813: R12.2 R13.1
N$16
  Top 0.813: R42.2 71.85,26.65 70.5,28 R46.2 R45.1
N$17
  Top 0.254: U4.4 24.74,47.74 24,47 C57.1
N$18
  Top 0.254: U4.3 24.25,48.25 23.25,47.25 22.35,47.25 R49.2 R51.1
N$19
  Top 0.61: L15.1 D32.2 107.2,24.77 D23.C D22.A 107.2,9.2 I2+.TP
N$20
  Top 0.61: L16.1 D32.1 112.8,24.82 D25.C D24.A 112.8,9.2 I2-.TP
N$21
  Top 0.61: L17.1 D33.2 127.2,24.77 D27.C D26.A 127.2,9.2 I3+.TP
N$22
  Top 0.61: L18.1 D33.1 132.8,24.82 D29.C D28.A 132.8,9.2 I3-.TP
N$23
  Top 0.254: X1.3 74.97,60.83 R16.1
N$24
  Top 0.406: JMP1.2 137.77,27.27 137.5,27 L18.2
  Top 0.61: RB2.2 133.5,27.5 134,27 L18.2 135.5,29.35 R21.1
N$25
  Top 0.254: U4.1 25.26,49.24 25,49.5 C61.1
N$26
  Top 0.61: L9.1 D13.1 92.8,24.82 D12.C D11.A 92.8,9.2 I1-.TP
N$27
  Top 0.61: RB1.1 113.5,27.5 114,27 L16.2 115.5,27.85 R34.1 R18.2
N$28
  Top 0.254: U4.2 22.34,48.76 R49.1
  Bottom 1.016: D5.C 12,48.59 C59.+
  pour Top (no thermals): 11.25,47.5 16.5,47.5 17,48 21,48 21.5,48.5 23,48.5 23,49.5 12.75,49.5 12.25,50 11.25,50 10.5,49.25 10.5,48.25
N$29
  Top 0.61: R2.2 R22.2 84.5,27.85 L8.2 86,27 86.5,27.5 RB3.2
N$30
  Top 0.406: R30.1 132,91.06
  Top 0.61: R30.1 R29.2 | T1.B 133.45,95.95 132,94.5 132,91.06
N$31
  Top 0.61: RB2.1 126.5,27.5 126,27 L17.2 124.5,29.35 R20.1
N$32
  Top 0.813: R44.2 47.85,26.65 46.5,28 R53.2 R50.1
N$33
  Bottom 1.016: D6.C D5.A 16.88,27.92 R54.2
N$34
  Bottom 1.016: R54.1 22.04,23.03 C60.2
N$35
  Top 0.254: U3.14 83.8,49.85 C3.2
N$36  (via drill 0.4)
  other vias: 33.75,53.75 33.75,52.75 33.75,51.5 33.75,50.5
  pour Top (no thermals): 25.5,52.5 25.5,54 29.5,54 29.5,49.25 31.5,49.25 31.5,49.75 34.5,49.75 34.5,55 24.5,55 24.5,52.5
  pour Bottom (no thermals): 33,54.5 33,49.5 37.5,49.5 39,51 39,53.5 37.5,55 33,55
N$37
  Top 0.61: R19.2 R23.1 95.5,27.85 L9.2 94,27 93.5,27.5 RB3.1
N$39
  Top 0.813: R38.2 R41.1
N$40
  Top 0.406: R56.2 R57.1
N$41
  Top 0.254: U4.7 31.01,47.74 31.5,47.25 31.5,45.6 R58.1
  Top 0.406: R58.1 R57.2
N$42
  Top 0.61: R17.2 R33.2 104.5,27.85 L15.2 106,27 106.5,27.5 RB1.2
N$43
  Top 0.254: R55.1 33.25,45.65 C63.2 32.35,47.15 32.25,47.25 31.25,48.25 U4.8
N$44
  Top 0.254: C62.2 35,45.6 R55.2
N$49
  Top 0.61: U2.2 119.86,89.64 119.25,90.25 R37.2
N$51
  Top 0.406: D2.1 15.97,150.03 15,151 USB2.1
N$52
  Top 0.254: RF3.3 128.56,126.56 128.25,126.25 R108.2
N$56
  Top 0.254: RF3.6 129.82,132.18 129,133 R77.1
N$57
  Top 0.254: RF3.8 131.09,132.41 130.5,133 R78.1
N$58
  Top 0.254: RF3.10 132.37,132.63 132,133 R79.1
N$60
  Top 0.254: RF3.12 133.63,132.87 133.5,133 R80.1
N$61
  Top 0.254: RF3.14 134.91,132.91 135,133 R81.1
N$62
  Top 0.254: RF3.16 136.18,132.68 136.5,133 R82.1
N$63
  Top 0.254: RF3.18 137.44,132.44 138,133 R83.1
N$64
  Top 0.254: RF3.20 138.72,132.22 139.5,133 R84.1
N$65
  Top 0.254: R85.2 137.5,161.57 RF4.18
N$104
  Top 0.813: LED_ACT.A R72.1
N$105
  Top 0.813: LED_REACT.A R73.1
N$108
  Top 0.254: R86.1 138.75,158.43 RF4.19
N$109
  Top 0.813: ISO_ACT.1 OK1.4
N$110
  Top 0.254: RF3.5 129.82,126.58 129.75,126.5 R105.2
N$111
  Top 0.254: RF3.7 131.09,126.66 131.25,126.5 R106.2
N$113
  Top 0.406: R76.2 20.15,61.85 20,62 19.73,62.27 OK2.2
N$114
  Top 0.406: R75.2 20.15,69.35 20,69.5 19.73,69.77 OK1.2
N$117
  Top 0.813: ISO_ACT.2 OK1.3
N$118
  Top 0.813: ISO_REACT.1 OK2.4
N$119
  Top 0.813: ISO_REACT.2 OK2.3
N$130
  Bottom 0.61: JTG_PWR1.3 145.29,45.29 148.6,45.29 J1.4
N$455
  Top 0.61: U2.3 118.19,88.36 T2.E
N_APP
  Bottom 1.016: NAPP.MP 30.5,176.93 R5.1 30.42,174.08 38,166.5 38.33,166.17 U$2.N
NEUTRAL_1
  Top 0.813: L6.1 74,12 N2.TP
O
  Top 0.254: JTAG_SEL6.2 140,48.75 136.54,48.75 FSEL1.1
P1.1  (via drill 0.4)
  Top 0.254: v127,50 126,51 113.5,51 106.5,58 81.5,58 80.28,56.77 U3.18
  Bottom 0.254: FSEL3.2 131.25,55 131.25,49.75 130.5,49 128,49 v127,50
P1.2
  Top 0.254: FSEL2.2 133.75,52 133.75,49.25 133,48.5 129.75,48.5 126.75,51.5 113.75,51.5 106.75,58.5 81.25,58.5 79.62,56.88 U3.19
P1.3
  Top 0.254: FSEL1.2 130.75,52 114,52 107,59 81,59 78.97,56.98 U3.20
PU.0/DP  (via drill 0.4)
  Top 0.254: R25.2 C39.1 R7.1 R6.2 v27.5,157.25 | U1.77 69,121 68.5,121.5 68.5,122.25 69,122.75 71.5,125.25 71.5,139 70,140.5 55,140.5 50.75,140.5 49,142.25 48.5,142.75 48.5,155 46.5,157 45.5,158 29,158 v28.75,158.25
  Bottom 0.254: v28.75,158.25 28.5,158.25 v27.5,157.25
PU.1/DM
  Top 0.254: C40.1 R35.1 25.75,151.25 26.5,152 26.5,155.5 27.5,156.5 29,156.5 30.5,156.5 45.5,156.5 46,156 47.5,154.5 47.5,142.25 48,141.75 50.25,139.5 55,139.5 69.5,139.5 70.5,138.5 70.5,125.75 67.5,122.75 67.5,121 68.5,120 U1.79
PUR
  Top 0.254: R6.1 22.9,157.9 23.5,158.5 26,158.5 27.5,158.5 28.5,157.25 29.5,157.25 33.5,157.25 45.5,157.25 46.25,156.5 48,154.75 48,142.5 48.5,142 50.5,140 55,140 69.75,140 71,138.75 71,125.5 69,123.5 68,122.5 68,121.25 68.75,120.5 U1.78
REACT_PUL
  Top 0.254: U3.27 74.42,57.08 74,57.5 27.73,57.5 REACT.1
  Top 0.406: REACT.1 22.77,59.73 22.35,60.15 R76.1
  Bottom 0.406: REACT.1 27.48,59.73 27.5,59.75 29,61.25 29.25,71 29.25,71.48 LED_REACT.K
RESETCC  (via drill 0.4)
  Top 0.254: U1.40 87.75,116.5 95,116.5 112,133.5 122.5,144 123.75,145.25 v129.75,145.25 v135.75,145.25 | v129.75,122 R105.1 | v136.25,150.25 R87.2
  Bottom 0.254: v129.75,145.25 v129.75,122 | v135.75,145.25 135.75,149.75 v136.25,150.25
RF_GPIO1  (via drill 0.4)
  Top 0.254: U1.36 87,114.5 96,114.5 113,131.5 122.75,141.25 v138.75,141.25 143.19,141.25 JP2.1 | v138.75,150.25 R86.2
  Bottom 0.254: v138.75,141.25 v138.75,150.25
RF_GPIO2  (via drill 0.4)
  Top 0.254: U1.37 95.75,115 112.75,132 123,142.25 v137.5,142.25 140.25,142.25 141.5,143.5 143.48,143.5 JP2.2 | v137.5,167.5 R85.1
  Bottom 0.254: v137.5,142.25 137.5,167 v137.5,167.5
ROSC
  Top 0.254: U3.11 80.28,48.98 81,48.25 81.75,48.25 82.25,47.75 R8.1
RST/NMI
  Top 0.254: U1.96 69,111.5 68.75,111.25 68.75,108.75 68,108 65,105 59.5,105 49.25,105 26.5,127.75 23,131.25 13.65,131.25 R14.2
  Top 1.016: R14.2 C24.2 9.6,130.1 9.5,130 8.5,129 8.5,128 8.5,124 7,122.5 2.5,122.5 1.5,123.5 1.5,126.5 2.42,127.42 JTAG2.11
RST/NMI_AFE
  Top 0.254: J1.11 152.17,56.58 151,57.75 148.54,57.75 JTAG_SEL2.1
RST_AFE  (via drill 0.4)
  Top 0.254: U3.15 82.22,56.23 82.5,56.5 84,56.5 | v123,49.25 122.75,49.5 112.75,49.5 105.75,56.5 86.5,56.5 | S4.1 | 84,56.5 86.5,56.5 | 86.5,56.5 R61.2 | 84,56.5 C27.1
  Top 0.406: JTAG_SEL2.2 140,63.75 127.26,63.75 S4.1 S4.2
  Bottom 0.305: S4.2 125.76,52.01 v123,49.25
RXD  (via drill 0.4)
  Top 0.61: D7.2 v140.23,87.5 CON1.3 | R36.2 v138.5,77
  Bottom 0.61: v140.23,87.5 140.23,78.73 v138.5,77
S0
  Top 0.254: U1.75 72,139.25 70.25,141 54.83,141 LCD1.1
S1
  Top 0.254: U1.74 72.5,139.5 70.5,141.5 56.87,141.5 LCD1.2
S2
  Top 0.254: U1.73 73,139.75 70.75,142 63.99,142 LCD1.5
S3
  Top 0.254: U1.72 73.5,140 71,142.5 66.03,142.5 LCD1.6
S4
  Top 0.254: LCD1.7 68.07,143 71.25,143 74,140.25 U1.71
S5
  Top 0.254: LCD1.9 71.65,143.35 74.5,140.5 U1.70
S6
  Top 0.254: LCD1.10 74.19,141.56 75,140.75 U1.69
S7
  Top 0.254: U1.68 75.5,136.25 75.5,138.25 77.75,140.5 80.31,143 LCD1.13
S8
  Top 0.254: U1.67 76,136 76,138 81,143 82.85,143 LCD1.14
S9
  Top 0.254: U1.66 76.5,135.75 76.5,137.75 81.25,142.5 84.89,142.5 LCD1.15
S10
  Top 0.254: U1.65 77,135.5 77,137.5 81.5,142 89.47,142 LCD1.17
S11  (via drill 0.4)
  Top 0.254: v78,121.75 78,122 78.5,122.5 U1.62 | v78,131.75 78,137.25 82.25,141.5 91.51,141.5 LCD1.18
  Bottom 0.254: v78,121.75 v78,131.75
S12  (via drill 0.4)
  Top 0.254: v79,121.75 U1.61 | v79,131.75 79,137 83,141 98.63,141 LCD1.21
  Bottom 0.254: v79,121.75 v79,131.75
S13  (via drill 0.4)
  Top 0.254: v80,121.75 80,122 79.5,122.5 U1.60 | v80,131.75 80,136.75 83.75,140.5 100.67,140.5 LCD1.22
  Bottom 0.254: v80,121.75 v80,131.75
SFD  (via drill 0.4)
  Top 0.254: U1.38 95.5,115.5 112.5,132.5 123.25,143.25 133.25,143.25 v133.5,143.25 138.75,143.25 141.5,146 143.48,146 JP2.3 | v133.5,139.5 R80.2
  Bottom 0.254: v133.5,143.25 v133.5,139.5
SIMO  (via drill 0.4)
  Top 0.254: U3.24 76.38,56.38 76.5,56.5 76.5,64.5 76,65 v76,67 76.5,67.5 76.5,74.75 76,75.25 69.75,75.25 68.36,76.64 ISO2.6
  Bottom 0.254: v76,67 84,67 84.5,67.5 84.5,72 86.5,74 86.58,74.08 COMMS_AFE.1
SOMI  (via drill 0.4)
  Top 0.254: ISO2.7 69.64,76.61 70.5,75.75 76.25,75.75 77,75 77,66.5 v76.75,66.25 76.75,65 77,64.75 77,56.5 77.03,56.48 U3.23
  Bottom 0.254: v76.75,66.25 84.25,66.25 85.25,67.25 85.25,70.25 86.54,71.54 COMMS_AFE.2
SPI_CLK  (via drill 0.4)
  Top 0.254: ISO1.6 77.36,75.39 77.5,75.25 v77.5,65.5 77.5,56.5 77.67,56.33 U3.22
  Bottom 0.254: v77.5,65.5 84.5,65.5 86,67 86,68.5 86.5,69 COMMS_AFE.3
SPI_CS  (via drill 0.4)
  Top 0.254: ISO1.7 78.64,75.89 78,75.25 78,66.25 78.25,66 v78.25,64.75 78,64.5 78,56.75 78.33,56.42 U3.21
  Bottom 0.254: v78.25,64.75 84.75,64.75 86,66 86.46,66.46 COMMS_AFE.4
TCK
  Top 0.254: U1.95 68.75,112 68.25,111.5 68.25,109 64.75,105.5 49.5,105.5 23.75,131.25 23.25,131.75 8.5,131.75 8,131.25 5,131.25 3.75,132.5 JTAG2.7
TCK_AFE
  Top 0.254: J1.7 152.25,51.5 151,52.75 148.75,52.75 145.5,56 145.5,57.79 JTAG_SEL3.1
  Bottom 0.254: JTAG_SEL3.1 144,59.25 142.5,57.75 140.46,57.75 JTAG_SEL1.3
TDI
  Top 0.254: U1.93 68.25,113 67.25,112 67.25,109.5 64.25,106.5 50,106.5 23.75,132.75 10.5,132.75 9,132.75 8,133.75 8,135.5 7.25,136.25 7,136.25 5,136.25 3.73,137.52 JTAG2.3
TDI_AFE
  Top 0.254: J1.3 152.27,46.48 151,47.75 146.54,47.75 JTAG_SEL5.1
TDO
  Top 0.254: U1.92 68,113.5 66.75,112.25 66.75,109.75 64,107 50.25,107 24,133.25 12.75,133.25 9.25,133.25 8.5,134 8.5,137.5 7.25,138.75 5,138.75 3.73,140.02 JTAG2.1
TDO_AFE
  Top 0.254: J1.1 152.12,44.13 151,45.25 146.04,45.25 JTAG_SEL6.1 144,47.25 142.75,48.5 142.75,60 142,60.75 140.46,60.75 JTAG_SEL2.3
TEST  (via drill 0.4)
  Top 0.254: U1.91 67.75,114 66.25,112.5 66.25,110 65.5,109.25 64.25,108 63.75,107.5 59.5,107.5 50.5,107.5 29,129 24.5,133.5 24.25,133.75 10,133.75 v9.5,134.25
  Bottom 0.254: v9.5,134.25 8.02,134.25 JTAG2.8
TEST/SBWTCK_AFE  (via drill 0.4)
  Top 0.254: U3.16 81.58,56.5 82.08,57 106,57 113,50 124,50 v125,49
  Bottom 0.254: JTAG_SEL1.2 140,54.75 138.5,54.75 137,53.25 137,49.5 135.5,48 126,48 v125,49
TEST_AFE
  Top 0.254: J1.8 148.79,51.5 JTAG_SEL1.1
TMS
  Top 0.254: U1.94 68.5,112.5 67.75,111.75 67.75,109.25 64.5,106 49.75,106 23.5,132.25 8.75,132.25 7.25,133.75 7,133.75 5,133.75 3.73,135.02 JTAG2.5
TMS_AFE
  Top 0.254: J1.5 152.27,48.98 151,50.25 147.04,50.25 JTAG_SEL4.1
TXD
  Top 0.61: CON1.2 140.47,90 R31.2 R32.1
UART_RX  (via drill 0.4)
  Top 0.61: U5.6 v119.5,83.14 118.19,83.14 R39.2
  Bottom 0.406: FSEL2.3 129.96,53.29 128.5,54.75 128.5,66 123.5,71 UART.2 120.5,74 119.5,75 v119.5,83.13 v119.5,83.14
UART_TX  (via drill 0.4)
  Top 0.406: R40.1 115.25,84.75 v114,83.5
  Bottom 0.254: UART.1 121.29,70.71
  Bottom 0.406: FSEL1.3 129.96,50.29 127.5,52.75 127.5,64.46 UART.1 114,77.96 v114,83.5
V1
  Top 0.813: R41.2 R44.1
V1+  (via drill 0.4)
  Top 0.305: U3.1 73.78,48.77 72.5,47.5 72.5,47
  Top 0.406: C41.1 v40.35,33.1 | v42.25,35 61.75,35 62,35 64,37 69,37 70,38 70,40 72.5,42.5 72.5,45.5 72.5,47
  Top 0.813: R50.2 C13.1 C41.1
  Bottom 0.406: v40.35,33.1 v42.25,35
V1-
  Top 0.305: U3.2 74.42,48.42 73.5,47.5 73.5,47
  Top 0.406: C41.2 38.65,33.15 39.5,34 40.5,34 62.25,34 64.25,36 69.5,36 71,37.5 71,39.5 73.5,42 73.5,45.5 73.5,47
  Top 0.813: R47.1 C14.2 C41.2
V2
  Top 0.813: R13.2 R42.1
V2+
  Top 0.406: C56.1 64.35,33.1 65.25,34 70,34 70.5,34 72.5,36 73,36.5 JMP2.3
  Top 0.813: R45.2 C16.1 C56.1
V2-
  Top 0.406: C56.2 62.65,32.9 64.75,35 70,35 72,37 72,39 72.5,39.5 JMP3.3
  Top 0.813: R43.1 C19.2 C56.2
VBUS  (via drill 0.4)
  Top 0.254: IC7.6 18.23,153.77 v18,154 | U1.80 68.25,119.5 67,120.75 67,123 70,126 70,138.25 69.25,139 50,139 47,142 47,154.25 45.5,155.75 30.5,155.75
  Top 0.406: 30.5,155.75 28.9,154.15 C42.1 C43.1 27.5,149.75 25.25,147.5 22,147.5 21,148.5 21,149.88 D2.2 20.88,151.12 v20,152
  Bottom 0.406: v20,152 v18,154
VCC_AFE  (via drill 0.4, 0.6)
  Top 0.254: X1.4 70.95,62.3 C4.1 71.25,62.5
  Top 0.305: U3.13 81.58,49.17 82.5,48.25 C10.2 | v86.5,53.25 R61.1
  Top 0.406: 89,80 ISO3.8 88.91,78.25 C25.2 89,78 89.24,77.76 v89.24,76.75 | v71.25,76.75 71.25,77.9 C52.2 70.91,78.25 ISO2.8 | ISO1.8 79.91,78.25 C55.2 80,78 80.23,77.77 v80.23,76.75
  Top 0.61: U5.8 119.91,80.59 119.5,81 118.06,81 R39.1 C54.2
  Top 0.813: R72.2 14.85,82.35 15,82.5 | R73.2 30.85,82.35 31,82.5
  Top 1.016: v81.5,16 D9.C | D22.C v100,16 D11.C | D24.C v120.5,16 D26.C | D28.C v139,16 143.5,20.5 143.5,31 139,35.5 135.5,35.5 132.5,38.5 132.5,42.5 | 111.5,81.06 C54.2 | R37.1 114.75,90.25 111.5,87 111.5,81.06 | R10.2 v65,54 49.5,54 46.5,51 PWR1.2 | v71.25,65 71.25,62.5 | v111.5,76.75 111.5,81.06 | JTG_PWR1.2 132.75,42.75 132.5,42.5 | VCC_AFE.4 VCC_AFE.3 VCC_AFE.2 VCC_AFE.1 8.94,82.5 15,82.5 v17.5,82.5 31,82.5 48.75,82.5 54.5,76.75 v67,76.75 | v132.5,42.75 132.5,42.5 | v86.5,46.5 84.68,46.5 83.9,47.28 C10.2
  Bottom 0.305: v86.5,46.5 v86.5,53.25
  Bottom 1.016: v81.5,16 v100,16 v120.5,16 v139,16 | 72.25,76.75 v71.25,76.75 70.25,76.75 | 72.25,76.75 v80.23,76.75 v89.24,76.75 v111.5,76.75 116,72.25 116,46.5 | OK2.1 19.73,59.73 21,61 21,67.5 | OK1.1 20.73,67.23 21,67.5 | 21,67.5 21,73.5 17.5,77 v17.5,82.5 | 70.25,76.75 71.25,75.5 | 71.25,75.5 72.25,76.75 | v67,76.75 70.25,76.75 | 116,46.5 v86.5,46.5 | v65,54 65,60.76 69.24,65 v71.25,65 71.25,75.5 | 116,46.5 119.75,42.75 v132.5,42.75
VMON
  Top 0.254: U3.28 72.54,55.69 R10.1 R11.1
VREF
  Top 0.254: U3.9 78.97,48.88 C1.2
VREG_EN  (via drill 0.4)
  Top 0.254: U1.41 87,117 94.75,117 111.75,134 122.75,145 124,146.25 v128.25,146.25 | v128.25,122 R108.1
  Bottom 0.254: v128.25,146.25 v128.25,122
VUSB  (via drill 0.4)
  Top 0.254: U1.81 71.5,119 v73,117.5 | v69.5,108.5 65.5,104.5 49,104.5 26.5,127 25.65,127.85 R15.2
  Bottom 0.254: v73,117.5 73,112 v69.5,108.5
XIN
  Top 0.254: U1.13 78,106 77,105 XT1.P2 77,103.5 76.5,103 75.5,102 C29.1
XOUT
  Top 0.254: U1.14 78.5,106 79.5,105 XT1.P1 79.5,103.5 81,102 C28.2

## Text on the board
tPlace: MSP430i2040 Polyphase Energy Meter | VCC_APP | GND_APP | GND_APP | SFD | RF_GPIO2 | RF_GPIO1 | FET | EXT | Max Thrun / Aug 2013 | USB | PL | SIMO | SOMI | SPI_CLK | SPI_CS | 1 | APP_INT | 1 | GND_AFE | RX | SIMO | SOMI | TX | GND_AFE | SPI_CLK | SPI_CS | PRGM | AFE_INT | RUN | GND_AFE | RESET | EXT | PL | EXT | FET | SBW | JTAG | Danger | High Voltage | 120/240 Vrms | 120/240 Vrms | 50mA MAX | 50mA MAX | 50mA MAX | 50/60 Hz | 50/60 Hz
_tplace: FET | EXT | USB | PL | JTG_PWR2 | PWR2 | 14 | R108 | 1 | R105 | R106 | 2 | DVCC2 | 1 | R107 | RF3 | Q1 | JTAG2 | R15 | R84 | R77 | USB2 | C24 | C8 | R14 | R81 | R80 | R78 | R83 | R82 | C7 | R79 | R3 | ZD3 | C37 | C32 | R4 | C29 | U1 | C35 | XT1 | R87 | C44 | DGND2 | C45 | RF4 | R86 | 1 | 2,54 | R85 | C28 | COMMS_APP | C51 | C50 | 1 | 2 | 3 | 4 | C2 | 9 | 5 | C20 | C46 | LED2 | ISO3 | REACT | LAPP | C21 | R36 | R76 | OK2 | HDR2 | D3 | D4 | C54 | ISO2 | C22 | C55 | R73 | D1 | R72 | R75 | ISO1 | C52 | ACT | NAPP | D7 | C15 | R27 | R39 | R29 | F09 | 6 | 1 | R30 | C53 | HDR1 | U5 | R37 | 4 | LED1 | 3 | 2 | 1 | OK1 | J1 | R31 | C4 | U2 | SBW | T1 | X1 | R32 | JTAG | CON1 | R28 | COMMS_AFE | PRGM | R19 | 1 | T2 | RUN | R40 | R16 | C9 | S4 | C27 | D6 | C10 | EXT | R10 | PL | EXT | R11 | C59 | C12 | R61 | C11 | JTG_PWR1 | FET | R54 | D5 | PWR1 | U3 | R2 | C1 | DVCC | L3 | R8 | C3 | R38 | R53 | R50 | C13 | DGND | C31 | C41 | C17 | C30 | C18 | C34 | C33 | C60 | RB1 | R33 | R17 | R18 | R21 | C14 | D32 | R34 | R20 | RB2 | D33 | R41 | R44 | R47 | R12 | R46 | R45 | R24 | R26 | C16 | L15 | L16 | L17 | JMP1 | ELLCTV | CUR1- | D26 | D28 | L18 | C56 | D22 | D24 | D27 | D29 | L5 | L6 | D23 | CUR1+ | D25 | CUR2+ | CUR2- | R1 | L7 | C19 | L1 | N2 | L2 | L4 | N1 | R42 | R43 | R13
_bplace: R6 | C47 | R7 | IC7 | C42 | C39 | R25 | R9 | C48 | C40 | C43 | D2 | R35 | C36 | C38 | C5 | C6 | VO- | VO+ | 22 | 26 | N | L | NC | R5 | U4 | * | R55 | C61 | D8 | C62 | R52 | C57 | R51 | R49 | C63 | C64 | R57 | C58 | R56 | R58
